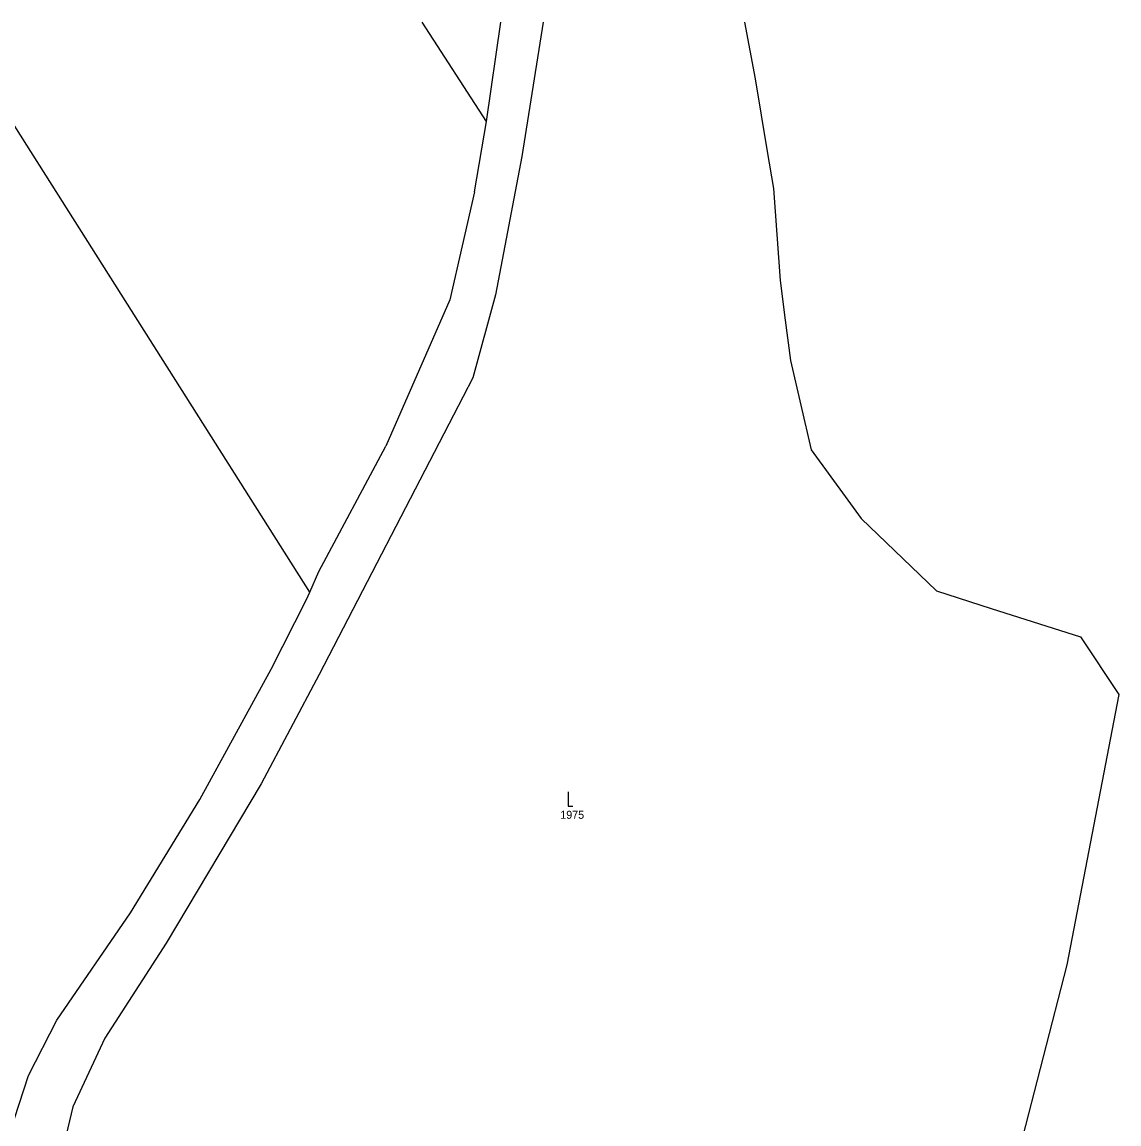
# Model space of a CAD drawing. Extents: x -801853 to -800578, y -1017479 to -1016338.
# Drawn here: x -801418.1 to -801185.1, y -1016571.7 to -1016337.6 of the extents above; entities that cross this region are included whole.
import ezdxf

# ---------------------------------------------------------------- set-up
doc = ezdxf.new("R2010")
doc.units = 0
for name, color, linetype in [('Default', 7, 'Continuous'), ('KN_HRANICE', 7, 'Continuous'), ('KN_KULTURY', 7, 'Continuous'), ('KN_PARCELY', 7, 'Continuous')]:
    doc.layers.add(name, color=color, linetype=linetype)

# ---------------------------------------------------------------- blocks, each defined once
blk = doc.blocks.new('302')
at = {"layer": 'Default'}
blk.add_lwpolyline([(0, 3), (0, 0), (1, 0)], dxfattribs=at)

msp = doc.modelspace()

# ---------------------------------------------------------------- linework, layer by layer
at = {"layer": 'KN_HRANICE'}
for p, q in [((-801356.93, -1016458.73), (-801433.65, -1016337.63)), ((-801319.43, -1016358.75), (-801333.04, -1016337.63)), ((-801319.43, -1016358.75), (-801316.33, -1016337.63)), ((-801307.4, -1016337.63), (-801311.92, -1016366.18)), ((-801264.62, -1016337.63), (-801262.33, -1016349.67)), ((-801262.33, -1016349.67), (-801259.75, -1016365.1)), ((-801321.94, -1016373.73), (-801319.43, -1016358.75)), ((-801311.92, -1016366.18), (-801317.51, -1016395.6)), ((-801259.75, -1016365.1), (-801258.44, -1016372.97)), ((-801258.44, -1016372.97), (-801257.05, -1016392.52)), ((-801321.94, -1016373.73), (-801327.21, -1016396.62)), ((-801257.05, -1016392.52), (-801255.96, -1016400.96)), ((-801327.21, -1016396.62), (-801340.82, -1016427.74)), ((-801317.51, -1016395.6), (-801322.34, -1016413.23)), ((-801255.96, -1016400.96), (-801254.86, -1016409.5)), ((-801254.86, -1016409.5), (-801250.45, -1016428.49)), ((-801322.34, -1016413.23), (-801326.45, -1016421.12)), ((-801326.45, -1016421.12), (-801354.97, -1016476.24)), ((-801355.05, -1016454.39), (-801340.82, -1016427.74)), ((-801250.45, -1016428.49), (-801242.64, -1016439.22)), ((-801242.64, -1016439.22), (-801239.82, -1016443.1)), ((-801239.82, -1016443.1), (-801223.83, -1016458.49)), ((-801356.93, -1016458.73), (-801355.05, -1016454.39)), ((-801357.62, -1016460.33), (-801356.93, -1016458.73)), ((-801223.83, -1016458.49), (-801212.17, -1016462.19)), ((-801365.17, -1016475.08), (-801357.62, -1016460.33)), ((-801212.17, -1016462.19), (-801193.22, -1016468.21)), ((-801193.22, -1016468.21), (-801185.05, -1016480.49)), ((-801380.3, -1016502.77), (-801365.17, -1016475.08)), ((-801354.97, -1016476.24), (-801367.28, -1016499.46)), ((-801185.05, -1016480.49), (-801196.12, -1016537.94)), ((-801367.28, -1016499.46), (-801387.43, -1016533.33)), ((-801395.02, -1016526.89), (-801380.3, -1016502.77)), ((-801410.71, -1016549.67), (-801395.02, -1016526.89)), ((-801387.43, -1016533.33), (-801400.48, -1016553.49)), ((-801196.12, -1016537.94), (-801207.69, -1016582.91)), ((-801416.73, -1016561.43), (-801410.71, -1016549.67)), ((-801400.48, -1016553.49), (-801407.27, -1016568.09)), ((-801419.68, -1016570.55), (-801416.73, -1016561.43)), ((-801407.27, -1016568.09), (-801410.39, -1016580.85))]:
    msp.add_line(p, q, dxfattribs=at)

# ---------------------------------------------------------------- block references
at = {"layer": 'KN_KULTURY'}
msp.add_blockref('302', (-801302.09, -1016504.19), dxfattribs=at)

# ---------------------------------------------------------------- texts
at = {"layer": 'KN_PARCELY'}
msp.add_text('1975', height=1.7, dxfattribs=at).set_placement((-801303.73, -1016506.89))

doc.saveas('drawing.dxf')
